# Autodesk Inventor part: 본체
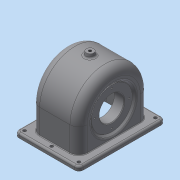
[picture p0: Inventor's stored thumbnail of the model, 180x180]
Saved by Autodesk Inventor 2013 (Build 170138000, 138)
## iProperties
Created: 2015-09
Part Number: 본체
Material: 일반
Document SubType Name: Modeling
Designer: dgall
Density: 1 g/cm^3
Author: dgall
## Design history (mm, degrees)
sketch "스케치1"
  geometry: L1 (-52, 70)-(52, 70); L2 (52, 70)-(52, -70); L3 (52, -70)-(-52, -70); L4 (-52, -70)-(-52, 70); 3 further points
  constraints: 8 end point, 2 midpoint, 2 parallel, 1 horizontal, 1 horizontal alignment, 1 perpendicular, 1 vertical alignment
  dimensions: "d0" = 104 distance of L1.start L1.end; "d2" = 140 distance of L1.end L2.end
extrude "돌출1" new body sketch "스케치1" distance "d3" = 7; taper "d4" = 0 deg
sketch "스케치2"
  geometry: L1 (70, 7)-(-70, 7) reference; L2 (-57, 7)-(-57, 47); L3 (57, 47)-(57, 7); L4 (-70, 0)-(70, 0) reference; A1 r 57 centre (0, 47) between (57, 47) and (-57, 47); 1 further point
  constraints: 4 end point, 2 perpendicular, 2 point on circle, 2 point on line, 2 tangent, 1 centre point, 1 vertical alignment
  dimensions: "d5" = 47 distance of point (0, 0) A1.centre; "d39" = 104 dimension on A1 L4
extrude "돌출2" join sketch "스케치2" stored distance "d7" = 77; taper "d8" = 0 deg
sketch "스케치3"
  geometry: L1 (-57, 7)-(-57, 47) reference; L2 (57, 47)-(57, 7) reference; L3 (-51, 0)-(-51, 47); L4 (51, 47)-(51, 0); L5 (-70, 0)-(70, 0) reference; A1 r 57 centre (0, 47) between (57, 47) and (-57, 47) reference; A2 r 51 centre (0, 47) between (51, 47) and (-51, 47); 1 further point
  constraints: 4 end point, 2 point on circle, 2 point on line, 1 centre point
  dimensions: "d9" = 6 radial gap between concentric circles of A2 A1; "d10" = 6 distance between parallel lines of L3 L1; "d11" = 6 distance between parallel lines of L2 L4
extrude "돌출3" cut sketch "스케치3" stored distance "d12" = 67; taper "d13" = 0 deg
sketch "스케치4"
  geometry: C1 r 31 at (47, 0); A1 r 57 centre (47, 0) between (47, -57) and (47, 57) reference; 1 further point
  constraints: 1 centre point, 1 coincident
  dimensions: "d14" = 62 diameter of C1
extrude "돌출4" join sketch "스케치4" distance "d16" = 10; taper "d17" = 0 deg
sketch "스케치6"
  geometry: C1 r 37.5 at (-47, 0); A1 r 57 centre (-47, 0) between (-47, 57) and (-47, -57) reference; 1 further point
  constraints: 1 centre point, 1 coincident
  dimensions: "d27" = 75 diameter of C1
extrude "돌출5" cut sketch "스케치6" distance "d29" = 5; taper "d30" = 0 deg
sketch "스케치7"
  geometry: L1 (-38.5, 104)-(-38.5, 47) reference; L2 (38.5, 47)-(38.5, 104) reference; L3 (-38.5, 47)-(38.5, 47); L4 (-38.5, 90.943)-(-19.5, 75); L5 (-19.5, 75)-(-19.5, 47); L6 (-35.5, 80)-(-35.5, 47); L7 (-38.5, 84.416)-(-33.237, 80); L8 (-33.237, 80)-(-35.5, 80); 1 further point
  constraints: 12 end point, 4 perpendicular, 4 point on line, 1 parallel
  dimensions: "d31" = 3 distance between parallel lines of L6 L1; "d32" = 16 distance between parallel lines of L5 L6; "d33" = 50 deg angle of L5 L4; "d34" = 56 diameter of L4.end L3; "d35" = 66 diameter of L6.start L3; "d37" = 5 distance between parallel lines of L7 L4
revolve "회전2" sketch "스케치7" stored, may be unused: angle "d36" = 90 deg
node "작업 평면1"
sketch "스케치8"
  geometry: C1 r 6 at (0, 0); 1 further point
  constraints: 1 centre point, 1 coincident
  dimensions: "d41" = 12 diameter of C1
extrude "돌출6" join sketch "스케치8" stored distance "d43" = 3; taper "d44" = 10 deg
hole "구멍1" diameter "d47" = 4.459; stored, may be unused: countersink angle "d51" = 90 deg, drill point angle "d53" = 118 deg; dims "d48" = 6, "d49" = 4, "d50" = 2, "d52" = 8, "d110" = 10, "d111" = 10
sketch "스케치9"
  geometry: C1 r 2.5 at (-44, -62); C2 r 2.5 at (0, -62); C3 r 2.5 at (44, -62); 1 further point
  constraints: 3 centre point, 2 equal radius, 2 horizontal alignment, 1 vertical alignment
  dimensions: "d54" = 62 vertical distance of C1.centre point (0, 0); "d55" = 44 distance of C1.centre C2.centre; "d56" = 44 distance of C3.centre C2.centre; "d57" = 5 diameter of C1
extrude "돌출7" cut sketch "스케치9" stored distance "d58" = 3; taper "d59" = 0 deg
sketch "스케치10"
  geometry: C1 r 33 at (0, 0) reference; 2 further points
  constraints: 1 horizontal alignment
  dimensions: "d60" = 28 distance of C1.centre point (-28, 0)
hole "구멍2" sketch "스케치10" at (-28, 0) diameter "d61" = 2.459; stored, may be unused: countersink angle "d65" = 90 deg, drill point angle "d67" = 118 deg; dims "d62" = 7, "d63" = 4, "d64" = 2, "d66" = 9
sketch "스케치11"
  geometry: C1 r 31 at (0, 0) reference; 2 further points
  constraints: 1 horizontal alignment
  dimensions: "d71" = 24 distance of point (24, 0) C1.centre
hole "구멍3" sketch "스케치11" at (24, 0) diameter "d72" = 2.459; stored, may be unused: countersink angle "d76" = 90 deg, drill point angle "d78" = 118 deg; dims "d73" = 6, "d74" = 4, "d75" = 2, "d77" = 8
hole "구멍4" diameter "d84" = 40; stored, may be unused: countersink angle "d88" = 90 deg, drill point angle "d90" = 118 deg; dims "d85" = 6, "d86" = 4, "d87" = 2, "d89" = 8, "d91" = 10, "d92" = 10
sketch "스케치12"
  geometry: L1 (77, 40)-(77, 0) reference; L2 (-13.5, 47)-(90.5, 47) reference; 2 further points
  constraints: 1 other
  dimensions: "d95" = 30 distance from line of L2 point (38.5, 17); "d96" = 38.5 distance from line of point (38.5, 17) L1
feature "엠보싱1" sketch "스케치12" dims "d0" = 104, "d2" = 140, "d97" = 0.5, "d98" = 0
fillet "모깎기1" dims "d93" = 14
fillet "모깎기2" dims "d94" = 9
fillet "모깎기3" dims "d99" = 7
fillet "모깎기4" dims "d100" = 3
fillet "모깎기5" dims "d101" = 3
fillet "모깎기6" dims "d102" = 3
fillet "모깎기7" dims "d103" = 3
fillet "모깎기8" dims "d104" = 3
fillet "모깎기9" dims "d105" = 0.5
fillet "모깎기10" dims "d106" = 1
chamfer "모따기1" distance "d107" = 1; stored, may be unused: second distance "d108" = 2, angle "d109" = 45 deg
node "솔리드1"
mirror "대칭1"
pattern_circular "원형 패턴1" dims angle "d69" = 360 deg
pattern_circular "원형 패턴2" dims angle "d80" = 360 deg
